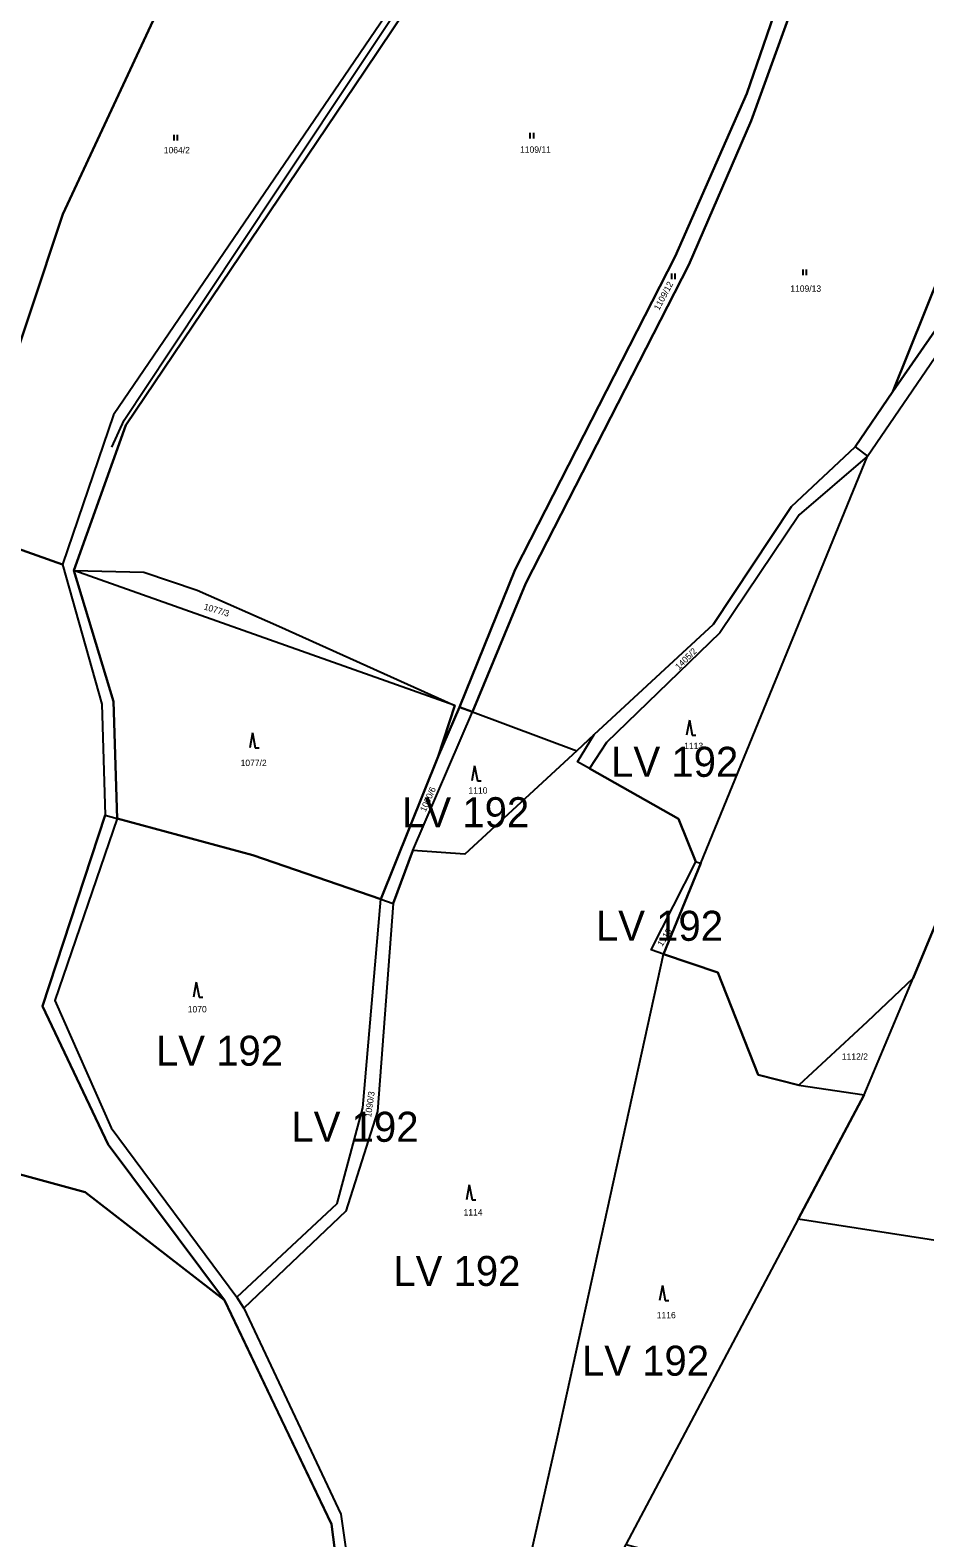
# Model space of a CAD drawing. Extents: x -588699 to -585793, y -1060280 to -1056731.
# Drawn here: x -588011.1 to -587772.5, y -1059422 to -1059020.2 of the extents above; entities that cross this region are included whole.
import ezdxf

# ---------------------------------------------------------------- set-up
doc = ezdxf.new("R2010")
doc.units = 0
for name, color, linetype in [('Druh pozemku', 7, 'Continuous'), ('Parcela nároku', 7, 'Continuous'), ('Vnitřní obvod', 7, 'Continuous'), ('Vnější obvod_převzatý', 7, 'Continuous')]:
    doc.layers.add(name, color=color, linetype=linetype)

msp = doc.modelspace()

# ---------------------------------------------------------------- linework, layer by layer
at = {"layer": 'Druh pozemku'}
for p, q in [((-587877.8, -1059047.52), (-587877.8, -1059049.02)), ((-587876.78, -1059049.02), (-587876.78, -1059047.52)), ((-587972.76, -1059048.06), (-587972.76, -1059049.56)), ((-587971.73, -1059049.56), (-587971.73, -1059048.06)), ((-587840.06, -1059085.02), (-587840.06, -1059086.52)), ((-587839.04, -1059086.52), (-587839.04, -1059085.02)), ((-587805.06, -1059084), (-587805.06, -1059085.5)), ((-587804.04, -1059085.5), (-587804.04, -1059084)), ((-587835.28, -1059204.08), (-587836.02, -1059208.08)), ((-587835.28, -1059204.08), (-587834.55, -1059208.08)), ((-587951.76, -1059207.51), (-587952.49, -1059211.51)), ((-587951.76, -1059207.51), (-587951.03, -1059211.51)), ((-587834.55, -1059208.08), (-587833.55, -1059208.08)), ((-587951.03, -1059211.51), (-587950.03, -1059211.51)), ((-587892.55, -1059216.27), (-587893.29, -1059220.27)), ((-587892.55, -1059216.27), (-587891.82, -1059220.27)), ((-587891.82, -1059220.27), (-587890.82, -1059220.27)), ((-587966.76, -1059273.95), (-587967.49, -1059277.95)), ((-587966.76, -1059273.95), (-587966.03, -1059277.95)), ((-587966.03, -1059277.95), (-587965.03, -1059277.95)), ((-587893.96, -1059327.92), (-587894.7, -1059331.92)), ((-587893.96, -1059327.92), (-587893.23, -1059331.92)), ((-587893.23, -1059331.92), (-587892.23, -1059331.92)), ((-587842.48, -1059354.77), (-587843.21, -1059358.77)), ((-587842.48, -1059354.77), (-587841.75, -1059358.77)), ((-587841.75, -1059358.77), (-587840.75, -1059358.77))]:
    msp.add_line(p, q, dxfattribs=at)
at = {"layer": 'Parcela nároku'}
for points in [[(-587889.64, -1058977.16), (-587988.8, -1059122.67), (-588002.41, -1059162.6), (-587991.92, -1059199.8), (-587991.04, -1059229.45), (-587987.84, -1059230.31), (-587988.8, -1059199.09), (-587999.42, -1059164.21), (-587985.54, -1059125.5), (-587921.85, -1059031.04), (-587857.94, -1058935.91)], [(-587977.01, -1059014.9), (-588002.33, -1059069.22), (-588019.76, -1059121.36), (-588078.39, -1059098.35), (-588094.36, -1059092.49), (-588137.61, -1059076.62), (-588140.55, -1059085.56), (-588142.58, -1059097.51), (-588145.94, -1059096.21), (-588181.1, -1059082.65), (-588179.57, -1059077.35), (-588159.61, -1059038.12), (-588153.56, -1059020.13)], [(-587928.02, -1059439.21), (-587930.74, -1059418.41), (-587959.21, -1059358.7), (-587990.26, -1059317.2), (-588007.77, -1059280.29), (-587991.04, -1059229.45), (-587987.84, -1059230.31), (-588004.52, -1059278.78), (-587989.45, -1059312.74), (-587955.99, -1059357.88), (-587954.12, -1059360.79), (-587928.21, -1059415.76), (-587925.21, -1059436.78)], [(-587839.84, -1059648.06), (-587768.32, -1059611.67), (-587746.03, -1059603.7), (-587709.91, -1059596.69), (-587739.14, -1059596.09), (-587764.91, -1059586.03), (-587798.65, -1059574.2), (-587854, -1059564.31), (-587888.11, -1059559.41), (-587899.85, -1059548.13), (-587903.59, -1059525.19), (-587921.92, -1059466.34), (-587928.02, -1059439.21), (-587930.74, -1059418.41), (-587959.21, -1059358.7), (-587996.36, -1059329.94), (-588040.14, -1059318.01)]]:
    msp.add_lwpolyline(points, dxfattribs=at)
for points in [[(-587800.01, -1058977.56), (-587812.23, -1058985.89), (-587822.27, -1058973.22), (-587819.38, -1058958.28), (-587833.41, -1058946.87), (-587857.94, -1058935.91), (-587921.85, -1059031.04), (-587985.54, -1059125.5), (-587999.42, -1059164.21), (-587980.79, -1059164.61), (-587966.55, -1059169.47), (-587944.72, -1059179.02), (-587897.85, -1059200.19), (-587902.23, -1059213.76), (-587896.62, -1059200.63), (-587881.71, -1059163.96), (-587839.09, -1059080.55), (-587819.95, -1059037.06), (-587810.06, -1059008.37), (-587794.76, -1058980.28)], [(-587924.68, -1058974.72), (-587905.4, -1058946.63), (-587884.31, -1058968.74), (-587889.64, -1058977.16), (-587988.8, -1059122.67), (-588002.41, -1059162.6), (-588025.52, -1059154.45), (-588014.35, -1059123.9), (-588019.76, -1059121.36), (-588002.33, -1059069.22), (-587977.01, -1059014.9), (-587930.6, -1058991.62)], [(-587792.35, -1058982.44), (-587794.76, -1058980.28), (-587810.06, -1059008.37), (-587819.95, -1059037.06), (-587839.09, -1059080.55), (-587881.71, -1059163.96), (-587896.62, -1059200.63), (-587893.09, -1059201.89), (-587878.87, -1059167.56), (-587835.47, -1059082.69), (-587818.85, -1059044.36), (-587806.74, -1059010.91)], [(-587746.69, -1059031.08), (-587763.53, -1059008.26), (-587792.35, -1058982.44), (-587806.74, -1059010.91), (-587818.85, -1059044.36), (-587835.47, -1059082.69), (-587878.87, -1059167.56), (-587893.09, -1059201.89), (-587865.33, -1059212.23), (-587860.66, -1059207.91), (-587828.89, -1059178.55), (-587808.03, -1059147.17), (-587791.1, -1059131.22), (-587781.05, -1059116.53)], [(-587732.73, -1059052.34), (-587746.69, -1059031.08), (-587781.05, -1059116.53), (-587741.45, -1059059.54)], [(-587730.92, -1059055.1), (-587719.69, -1059072.18), (-587704.11, -1059098.77), (-587719.73, -1059138.78), (-587733.74, -1059179.01), (-587755.32, -1059224.12), (-587765.29, -1059248.09), (-587775.58, -1059272.85), (-587787.87, -1059284.49), (-587806.06, -1059301.41), (-587816.93, -1059298.59), (-587827.73, -1059271.33), (-587842.17, -1059266.45), (-587832.19, -1059242.19), (-587787.81, -1059133.7), (-587738.62, -1059061.84)], [(-587730.92, -1059055.1), (-587732.73, -1059052.34), (-587741.45, -1059059.54), (-587781.05, -1059116.53), (-587791.1, -1059131.22), (-587787.81, -1059133.7), (-587738.62, -1059061.84)], [(-587865.13, -1059215.19), (-587860.66, -1059207.91), (-587828.89, -1059178.55), (-587808.03, -1059147.17), (-587791.1, -1059131.22), (-587787.81, -1059133.7), (-587806.04, -1059149.38), (-587827.16, -1059180.86), (-587857.36, -1059210.01), (-587861.94, -1059216.99)], [(-587787.81, -1059133.7), (-587806.04, -1059149.38), (-587827.16, -1059180.86), (-587857.36, -1059210.01), (-587861.94, -1059216.99), (-587838.15, -1059230.4), (-587833.53, -1059241.85), (-587832.19, -1059242.19)], [(-588025.52, -1059154.45), (-588002.41, -1059162.6), (-587991.92, -1059199.8), (-587991.04, -1059229.45), (-588007.77, -1059280.29), (-587990.26, -1059317.2), (-587959.21, -1059358.7), (-587996.36, -1059329.94), (-588040.14, -1059318.01), (-588084.15, -1059319.81), (-588082.84, -1059295.57), (-588061.98, -1059213.18), (-588028.43, -1059153.42)], [(-587897.85, -1059200.19), (-587999.42, -1059164.21), (-587988.8, -1059199.09), (-587987.84, -1059230.31), (-587951.68, -1059240.06), (-587917.52, -1059251.81), (-587902.23, -1059213.76)], [(-587980.79, -1059164.61), (-587966.55, -1059169.47), (-587944.72, -1059179.02), (-587897.85, -1059200.19), (-587999.42, -1059164.21)], [(-587902.23, -1059213.76), (-587917.52, -1059251.81), (-587914.23, -1059252.94), (-587909.02, -1059238.86), (-587893.09, -1059201.89), (-587896.62, -1059200.63)], [(-587909.02, -1059238.86), (-587893.09, -1059201.89), (-587865.33, -1059212.23), (-587895.18, -1059239.83)], [(-587842.17, -1059266.45), (-587845.46, -1059265.3), (-587833.53, -1059241.85), (-587838.15, -1059230.4), (-587861.94, -1059216.99), (-587865.13, -1059215.19), (-587860.66, -1059207.91), (-587865.33, -1059212.23), (-587895.18, -1059239.83), (-587909.02, -1059238.86), (-587914.23, -1059252.94), (-587918.47, -1059308.44), (-587926.9, -1059334.98), (-587954.12, -1059360.79), (-587928.21, -1059415.76), (-587925.21, -1059436.78), (-587919.59, -1059465.05), (-587900.11, -1059526.15), (-587870.48, -1059395.09)], [(-587951.68, -1059240.06), (-587987.84, -1059230.31), (-588004.52, -1059278.78), (-587989.45, -1059312.74), (-587955.99, -1059357.88), (-587929.23, -1059332.96), (-587922.35, -1059307.43), (-587917.52, -1059251.81)], [(-587833.53, -1059241.85), (-587832.19, -1059242.19), (-587842.17, -1059266.45), (-587845.46, -1059265.3)], [(-587765.29, -1059248.09), (-587718.04, -1059266.82), (-587743.83, -1059298.54), (-587761.07, -1059344.1), (-587806.31, -1059337.1), (-587788.7, -1059303.94), (-587775.58, -1059272.85)], [(-587929.23, -1059332.96), (-587922.35, -1059307.43), (-587917.52, -1059251.81), (-587914.23, -1059252.94), (-587918.47, -1059308.44), (-587926.9, -1059334.98), (-587954.12, -1059360.79), (-587955.99, -1059357.88)], [(-587827.73, -1059271.33), (-587816.93, -1059298.59), (-587806.06, -1059301.41), (-587788.7, -1059303.94), (-587806.31, -1059337.1), (-587852.2, -1059423.82), (-587857.57, -1059433.96), (-587862.35, -1059453.57), (-587890.68, -1059508.15), (-587900.11, -1059526.15), (-587870.48, -1059395.09), (-587842.17, -1059266.45)], [(-587775.58, -1059272.85), (-587787.87, -1059284.49), (-587806.06, -1059301.41), (-587788.7, -1059303.94)], [(-587761.07, -1059344.1), (-587806.31, -1059337.1), (-587852.2, -1059423.82), (-587694.77, -1059464.3), (-587693.56, -1059462.51), (-587684.97, -1059445.32), (-587677.03, -1059432.29), (-587674.16, -1059420.27), (-587715.8, -1059399.93), (-587725.62, -1059395.13), (-587724.26, -1059381.34), (-587744.43, -1059353.69)]]:
    msp.add_lwpolyline(points, close=True, dxfattribs=at)
at = {"layer": 'Vnitřní obvod'}
msp.add_lwpolyline([(-587989.32, -1059131.36), (-587985.98, -1059124.11), (-587973.69, -1059105.62), (-587945.03, -1059062.5), (-587897.58, -1058991.12)], dxfattribs=at)
at = {"layer": 'Vnější obvod_převzatý'}
for points in [[(-588203.27, -1059330.87), (-588149.16, -1059326.19), (-588084.15, -1059319.81), (-588040.14, -1059318.01), (-587996.36, -1059329.94), (-587959.21, -1059358.7), (-587944.98, -1059388.56), (-587930.74, -1059418.41), (-587929.38, -1059428.81), (-587928.02, -1059439.21), (-587921.92, -1059466.34), (-587912.76, -1059495.76), (-587903.59, -1059525.19)], [(-587806.31, -1059337.1), (-587852.2, -1059423.82), (-587857.57, -1059433.96), (-587862.35, -1059453.57), (-587890.68, -1059508.15), (-587900.11, -1059526.15), (-587896.89, -1059547.44), (-587890.31, -1059553.7), (-587887.13, -1059556.79), (-587860.57, -1059560.7)]]:
    msp.add_lwpolyline(points, dxfattribs=at)

# ---------------------------------------------------------------- texts
at = {"layer": 'Parcela nároku'}
for s, p in [('1064/2', (-587975.42, -1059053)), ('1109/11', (-587880.43, -1059052.87)), ('1109/13', (-587808.37, -1059089.92)), ('1113', (-587836.67, -1059211.81)), ('1077/2', (-587954.94, -1059216.33)), ('1110', (-587894.18, -1059223.68)), ('1070', (-587969.04, -1059282)), ('1112/2', (-587794.63, -1059294.62)), ('1114', (-587895.49, -1059336.13)), ('1116', (-587843.98, -1059363.53))]:
    msp.add_text(s, height=1.7, dxfattribs=at).set_placement(p)
for s, rotation, p in [('1109/12', 62.0357, (-587843.37, -1059095.02)), ('1077/3', 343.0809, (-587964.91, -1059174.55)), ('1405/2', 44.6344, (-587838.08, -1059190.78)), ('1090/6', 65.9594, (-587905.63, -1059228.7)), ('1115', 57.6125, (-587842.55, -1059264.58)), ('1090/3', 81.9981, (-587920.14, -1059310.05))]:
    msp.add_text(s, height=1.7, rotation=rotation, dxfattribs=at).set_placement(p)
at = {"layer": 'Vnější obvod_převzatý'}
for p in [(-587856.15, -1059219.2), (-587911.88, -1059232.63), (-587860.21, -1059262.91), (-587977.52, -1059296.2), (-587941.4, -1059316.48), (-587914.23, -1059354.9), (-587863.94, -1059378.82)]:
    msp.add_text('LV 192', height=8, dxfattribs=at).set_placement(p)

doc.saveas('drawing.dxf')
